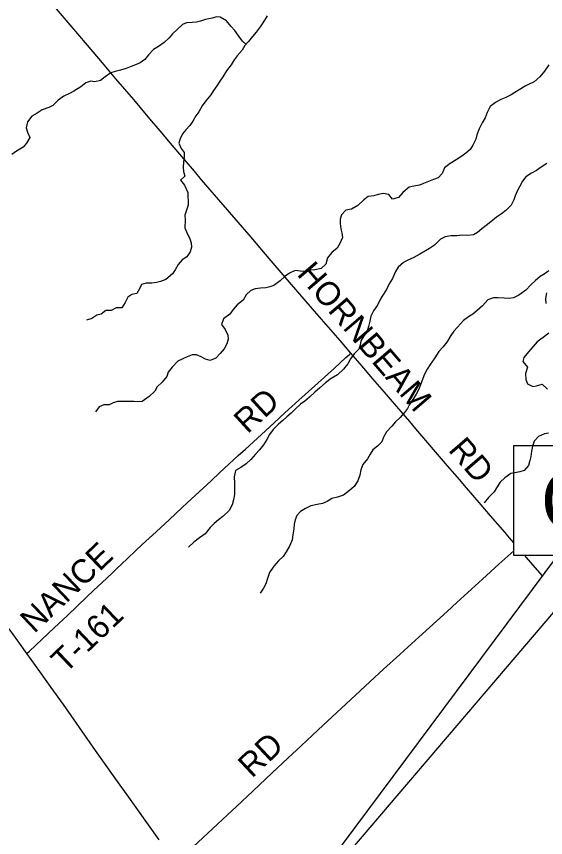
# Model space of a CAD drawing. Extents: x 0 to 34, y 0 to 22.
# Drawn here: x 5.101 to 6.367, y 18.098 to 20.064 of the extents above; entities that cross this region are included whole.
import ezdxf

# ---------------------------------------------------------------- set-up
doc = ezdxf.new("R2010")
doc.units = 0
for name, color, linetype in [('GM_X_Minor_River', 7, 'Continuous'), ('GM_X_State_Route', 7, 'Continuous'), ('GM_X_Township_Road', 7, 'Continuous'), ('GM_X_Township_Road_Text', 7, 'Continuous'), ('SH_Text', 7, 'Continuous')]:
    doc.layers.add(name, color=color, linetype=linetype)

msp = doc.modelspace()

# ---------------------------------------------------------------- linework, layer by layer
at = {"layer": 'GM_X_Minor_River'}
for points in [[(5.6499, 19.9972), (5.6422, 20.0042), (5.6332, 20.0168), (5.6234, 20.0298), (5.6148, 20.0397), (5.6035, 20.0535), (5.5887, 20.0616), (5.5793, 20.0628), (5.569, 20.0598), (5.553, 20.0561), (5.5412, 20.052), (5.5317, 20.0498), (5.521, 20.0488), (5.5081, 20.0485), (5.4982, 20.0444), (5.4852, 20.0327), (5.4741, 20.0222), (5.4665, 20.0124), (5.4542, 20.0011), (5.4405, 19.992), (5.4286, 19.9842), (5.4172, 19.9717), (5.4083, 19.9608), (5.3973, 19.9525), (5.3854, 19.948), (5.3755, 19.9439), (5.3634, 19.9391), (5.3496, 19.9354), (5.3375, 19.9317), (5.3268, 19.9283), (5.3134, 19.9189), (5.302, 19.9103), (5.2887, 19.9074), (5.2792, 19.9086), (5.2666, 19.9049), (5.2552, 19.8955), (5.238, 19.8849), (5.2277, 19.8793), (5.214, 19.873), (5.2006, 19.8636), (5.188, 19.8508), (5.1781, 19.8459), (5.1628, 19.8399), (5.1502, 19.8324), (5.1376, 19.8246), (5.1273, 19.8113), (5.1245, 19.7973), (5.1275, 19.7867), (5.1327, 19.7741), (5.125, 19.7605), (5.1166, 19.7507), (5.1009, 19.7409), (5.0902, 19.7334)], [(5.7012, 20.0649), (5.6919, 20.0509), (5.6843, 20.0392), (5.6743, 20.026), (5.6658, 20.0158), (5.6559, 20.0041), (5.6471, 19.9939), (5.6409, 19.983), (5.629, 19.9694), (5.6221, 19.9596), (5.6148, 19.9478), (5.6033, 19.9335), (5.5948, 19.9191), (5.5879, 19.9089), (5.5806, 19.8976), (5.5726, 19.8866), (5.566, 19.8764), (5.5538, 19.8617), (5.5453, 19.85), (5.5372, 19.8356), (5.5299, 19.8258), (5.523, 19.8126), (5.5161, 19.8024), (5.5061, 19.7926), (5.4981, 19.7824), (5.4923, 19.7703), (5.4895, 19.7601), (5.4951, 19.7475)], [(6.3747, 19.9479), (6.3647, 19.9324), (6.3532, 19.9188), (6.3398, 19.9075), (6.328, 19.9015), (6.3184, 19.8967), (6.3039, 19.8877), (6.294, 19.8817), (6.2845, 19.876), (6.2719, 19.8697), (6.2597, 19.8645), (6.2475, 19.8577), (6.2349, 19.8483), (6.2272, 19.8336), (6.2229, 19.8211), (6.2152, 19.8086), (6.2083, 19.7946), (6.2028, 19.7802), (6.2001, 19.77), (6.1932, 19.7556), (6.1866, 19.7454), (6.1767, 19.7367), (6.1668, 19.7292), (6.153, 19.7202), (6.1385, 19.7116), (6.1255, 19.701), (6.1193, 19.6874), (6.1101, 19.6772), (6.0987, 19.6735), (6.0873, 19.6683), (6.0747, 19.6638), (6.0652, 19.6601), (6.0515, 19.6575), (6.0409, 19.6553), (6.0259, 19.6425), (6.0148, 19.6301), (6.0011, 19.6264), (5.9917, 19.6371), (5.9781, 19.6399), (5.9667, 19.6377), (5.9564, 19.6343), (5.9423, 19.6325), (5.932, 19.6246), (5.9182, 19.6107), (5.9026, 19.6025), (5.8889, 19.5999), (5.8789, 19.589), (5.8754, 19.5784), (5.8757, 19.5681), (5.8772, 19.5548), (5.8794, 19.5453), (5.8815, 19.5343), (5.875, 19.5203), (5.8688, 19.5089), (5.8554, 19.4988), (5.8455, 19.4859), (5.8412, 19.4708), (5.8301, 19.4598), (5.8152, 19.4569), (5.8042, 19.4559), (5.7913, 19.4533), (5.7799, 19.4538), (5.7678, 19.455), (5.7544, 19.4494), (5.7437, 19.4415), (5.7319, 19.4306), (5.717, 19.4197), (5.7075, 19.4163), (5.6979, 19.4141), (5.6846, 19.4131), (5.6725, 19.4117), (5.6618, 19.4076), (5.6503, 19.3974), (5.6434, 19.3845), (5.6293, 19.3732), (5.6193, 19.3623), (5.6112, 19.3506), (5.596, 19.3397), (5.5917, 19.3264), (5.6003, 19.3139), (5.607, 19.3005), (5.6074, 19.2906), (5.6042, 19.2796), (5.5981, 19.2679), (5.5885, 19.2566), (5.5781, 19.2457), (5.5644, 19.2397), (5.5534, 19.2428), (5.5428, 19.2486)], [(5.4951, 19.7475), (5.5019, 19.7379), (5.5022, 19.7262), (5.5006, 19.7155), (5.4997, 19.7019), (5.5008, 19.6924), (5.5041, 19.681), (5.4938, 19.6716), (5.5032, 19.6597), (5.511, 19.6422), (5.5109, 19.6327), (5.5116, 19.6217), (5.5115, 19.6122), (5.5076, 19.5997), (5.5041, 19.5879), (5.5048, 19.5769), (5.5039, 19.5572), (5.5091, 19.5439), (5.5147, 19.5339), (5.5188, 19.5218), (5.5195, 19.5111), (5.5164, 19.5001), (5.5083, 19.4881), (5.4976, 19.4809), (5.488, 19.4696), (5.4811, 19.4571), (5.4745, 19.4473), (5.4585, 19.4337), (5.4459, 19.4293), (5.4364, 19.4263), (5.425, 19.4253), (5.4113, 19.4254), (5.3999, 19.4216), (5.3953, 19.4114), (5.3887, 19.4001), (5.3769, 19.3979), (5.3674, 19.3919), (5.3608, 19.3787), (5.3528, 19.3658), (5.3399, 19.3663), (5.3273, 19.3599), (5.3147, 19.3596), (5.304, 19.351), (5.2934, 19.3484), (5.2812, 19.3401), (5.2686, 19.3368)], [(6.3698, 19.7114), (6.3568, 19.7031), (6.3457, 19.6945), (6.3331, 19.6881), (6.3202, 19.6799), (6.3117, 19.6693), (6.3044, 19.6561), (6.2994, 19.6451), (6.2944, 19.6345), (6.2909, 19.6246), (6.2851, 19.6122), (6.2721, 19.5993), (6.2614, 19.5914), (6.2499, 19.5832), (6.2361, 19.5719), (6.2247, 19.5629), (6.2147, 19.5553), (6.2044, 19.5467), (6.1945, 19.5411), (6.1812, 19.5393), (6.1675, 19.5401), (6.1546, 19.5387), (6.1406, 19.5388), (6.1269, 19.5359), (6.1154, 19.5303), (6.1017, 19.5163), (6.0894, 19.508), (6.0795, 19.5028), (6.0662, 19.4945), (6.0501, 19.4859), (6.0372, 19.4803), (6.0273, 19.4747), (6.0143, 19.4634), (6.0077, 19.4528), (6.0008, 19.4366), (5.9931, 19.4233), (5.9865, 19.4097), (5.9761, 19.3942), (5.9707, 19.3844), (5.9646, 19.3727), (5.9554, 19.3591), (5.9492, 19.3458), (5.9464, 19.3341), (5.9437, 19.3212), (5.9402, 19.3098), (5.9317, 19.2973), (5.9252, 19.2871), (5.9232, 19.2769), (5.9201, 19.2671), (5.909, 19.2558), (5.9001, 19.244), (5.8943, 19.2316), (5.8832, 19.2195), (5.8691, 19.2055), (5.8542, 19.1969), (5.8404, 19.1864), (5.8267, 19.1744), (5.8152, 19.1642), (5.8022, 19.1521), (5.7911, 19.1423), (5.7808, 19.1352), (5.7678, 19.1232), (5.7582, 19.1141), (5.7479, 19.1047), (5.738, 19.0964), (5.728, 19.0874), (5.715, 19.0746), (5.7066, 19.0629), (5.7004, 19.0504), (5.6923, 19.0379), (5.6823, 19.0258), (5.6728, 19.0153), (5.662, 19.0032), (5.6506, 18.9927), (5.6376, 18.984), (5.625, 18.9765), (5.6218, 18.961), (5.6228, 18.9462), (5.6231, 18.9329), (5.623, 18.9192), (5.6206, 18.9063), (5.6175, 18.8946), (5.6098, 18.8806), (5.5949, 18.8666), (5.5846, 18.8584)], [(6.3746, 19.4543), (6.3639, 19.4468), (6.354, 19.4412), (6.3433, 19.4314), (6.3318, 19.4208), (6.3199, 19.408), (6.3035, 19.396), (6.2905, 19.39), (6.2803, 19.3882), (6.2677, 19.389), (6.2529, 19.3903), (6.2427, 19.3903), (6.2293, 19.3851), (6.2159, 19.3708), (6.2033, 19.3599), (6.1934, 19.3508), (6.1831, 19.3441), (6.1709, 19.3358), (6.1567, 19.3196), (6.1479, 19.3098), (6.1402, 19.2996), (6.131, 19.2837)], [(6.3692, 19.4016), (6.3668, 19.3887), (6.3675, 19.3761)], [(6.3753, 19.3051), (6.3615, 19.2949), (6.3467, 19.2848), (6.3378, 19.2731), (6.326, 19.2606), (6.3148, 19.2471), (6.3129, 19.2376), (6.3238, 19.2238), (6.3195, 19.2091), (6.3201, 19.1946), (6.3242, 19.1843), (6.3363, 19.1774), (6.3458, 19.1792), (6.3588, 19.1829), (6.3716, 19.1711)], [(6.131, 19.2837), (6.1214, 19.2716), (6.1118, 19.2611), (6.1022, 19.2463), (6.091, 19.2305), (6.0834, 19.2195), (6.0776, 19.207), (6.0737, 19.1968), (6.0679, 19.1813), (6.0632, 19.1696), (6.0578, 19.1594), (6.0509, 19.1488), (6.0413, 19.1348), (6.0367, 19.125), (6.0297, 19.1151), (6.019, 19.1034), (6.0079, 19.0929), (5.9991, 19.0827), (5.9861, 19.0695), (5.9795, 19.0563), (5.9756, 19.0453), (5.9653, 19.0347), (5.9538, 19.0257), (5.9473, 19.0155), (5.9408, 19.0042), (5.93, 18.991), (5.9254, 18.9781), (5.923, 18.9652), (5.9179, 18.952), (5.9087, 18.9384), (5.8976, 18.9289), (5.8835, 18.9177), (5.8694, 18.9128), (5.8553, 18.9091), (5.8446, 18.9024), (5.8336, 18.8979), (5.8207, 18.8953), (5.8054, 18.892), (5.7925, 18.8857), (5.7803, 18.8786), (5.7718, 18.8684), (5.7676, 18.8585), (5.7652, 18.8483), (5.7644, 18.8369), (5.7627, 18.8221), (5.7607, 18.8104), (5.7553, 18.7967), (5.7465, 18.782), (5.7392, 18.7703), (5.7284, 18.7601), (5.7166, 18.7473), (5.7066, 18.7326), (5.7015, 18.7178), (5.6976, 18.7053), (5.6922, 18.6947), (5.6838, 18.6826)], [(5.5428, 19.2486), (5.5319, 19.2532), (5.5216, 19.2533), (5.5098, 19.2485), (5.4988, 19.244), (5.4873, 19.238), (5.4739, 19.2237), (5.4639, 19.212), (5.4604, 19.2017), (5.4497, 19.1878), (5.4378, 19.1765), (5.4321, 19.1666), (5.4183, 19.1535), (5.4019, 19.1418), (5.3909, 19.1408), (5.3814, 19.1416), (5.3673, 19.1421), (5.3525, 19.1418), (5.343, 19.1415), (5.3327, 19.1385), (5.3228, 19.1337), (5.3103, 19.1334), (5.2985, 19.1289), (5.29, 19.1172)], [(6.3738, 19.0659), (6.3643, 19.0644), (6.3502, 19.0581), (6.3402, 19.0468), (6.3356, 19.035), (6.3336, 19.0229), (6.3316, 19.0104), (6.3296, 19.0002), (6.3261, 18.9884), (6.3161, 18.9767), (6.3058, 18.9734), (6.2937, 18.9708), (6.2842, 18.9694), (6.2693, 18.9588), (6.2589, 18.9487), (6.2501, 18.9351), (6.2439, 18.9252), (6.2309, 18.9117), (6.2202, 18.8988)], [(5.5846, 18.8584), (5.5742, 18.8497), (5.5647, 18.8399), (5.5528, 18.8252), (5.5386, 18.8154), (5.5256, 18.8053), (5.5126, 18.7932)]]:
    msp.add_lwpolyline(points, dxfattribs=at)
at = {"layer": 'GM_X_State_Route'}
msp.add_lwpolyline([(5.4426, 18.0921), (5.3875, 18.1696), (5.3657, 18.1999), (5.3425, 18.2321), (5.3197, 18.2647), (5.2903, 18.3063), (5.2648, 18.3431), (5.2322, 18.39), (5.2134, 18.4163), (5.184, 18.4571), (5.1567, 18.4949), (5.126, 18.5381), (5.1045, 18.5683), (5.0834, 18.5976)], dxfattribs=at)
at = {"layer": 'GM_X_Township_Road'}
for points in [[(5.9015, 19.2573), (5.8758, 19.2875), (5.831, 19.3391), (5.8094, 19.364), (5.739, 19.4452), (5.706, 19.484), (5.6575, 19.5406), (5.6311, 19.5712), (5.6209, 19.5829), (5.5953, 19.6126), (5.5751, 19.6362), (5.5441, 19.6726), (5.5268, 19.693), (5.492, 19.7343), (5.4698, 19.7603), (5.445, 19.7897), (5.4204, 19.8186), (5.3814, 19.8646), (5.3391, 19.9142), (5.3065, 19.9525), (5.2707, 19.9947), (5.2012, 20.0767), (5.1664, 20.1181)], [(5.126, 18.5381), (5.1321, 18.5438), (5.1912, 18.5997), (5.2227, 18.6297), (5.2682, 18.673), (5.2863, 18.69), (5.3058, 18.7083), (5.3289, 18.73), (5.341, 18.7415), (5.3523, 18.7522), (5.3676, 18.7668), (5.3856, 18.7839), (5.402, 18.7991), (5.4353, 18.83), (5.4671, 18.8596), (5.4818, 18.873), (5.4977, 18.8878), (5.5096, 18.8988), (5.5669, 18.9521), (5.5879, 18.9716), (5.6094, 18.9913), (5.6317, 19.0121), (5.6491, 19.028), (5.6871, 19.0629), (5.7179, 19.091), (5.7435, 19.1144), (5.777, 19.1451), (5.8609, 19.2209), (5.8895, 19.2467), (5.8979, 19.2541), (5.9015, 19.2573)], [(6.2913, 18.8031), (6.2807, 18.8154), (6.2766, 18.8201), (6.2701, 18.8277), (6.2352, 18.8681), (6.2127, 18.8947), (6.1731, 18.9409), (6.1617, 18.954), (6.1326, 18.988), (6.057, 19.0762), (6.0421, 19.0937), (6.0113, 19.1295), (5.9959, 19.1474), (5.9814, 19.1644), (5.9536, 19.1963), (5.9233, 19.2317), (5.9015, 19.2573)], [(5.4835, 18.0361), (5.4951, 18.0472), (5.5055, 18.0579), (5.5234, 18.0751), (5.582, 18.1299), (5.6057, 18.1518), (5.6276, 18.172), (5.6664, 18.2087), (5.7125, 18.2523), (5.7503, 18.2874), (5.7819, 18.3173), (5.8228, 18.3554), (5.8901, 18.4181), (5.9581, 18.4809), (5.9796, 18.5007), (6.0181, 18.5359), (6.0287, 18.5455), (6.0638, 18.5772), (6.1316, 18.6392), (6.1545, 18.6602), (6.2166, 18.7166), (6.2556, 18.7523), (6.2913, 18.7845)], [(6.3598, 18.724), (6.3425, 18.7441), (6.3218, 18.768), (6.3172, 18.7733)]]:
    msp.add_lwpolyline(points, dxfattribs=at)
at = {"layer": 'SH_Text'}
msp.add_lwpolyline([(6.2913, 19.0362), (7.4233, 19.0362), (7.4233, 18.7733), (6.5017, 18.7733), (5.6692, 17.796), (6.3965, 18.7733), (6.2913, 18.7733)], close=True, dxfattribs=at)

# ---------------------------------------------------------------- texts
at = {"layer": 'GM_X_Township_Road_Text'}
for s, rotation, p in [('HORNBEAM', 310.6273, (5.7701, 19.4456)), ('RD', 42.5707, (5.6538, 19.0626)), ('RD', 310.8176, (6.1324, 19.0249)), ('NANCE', 43.5958, (5.1435, 18.5847)), ('T-161', 43.6196, (5.2177, 18.4888)), ('RD', 43.2429, (5.6643, 18.2381))]:
    msp.add_text(s, height=0.05682, rotation=rotation, dxfattribs=at).set_placement(p)
at = {"layer": 'SH_Text'}
msp.add_text('CLI-72-2.18', height=0.14, dxfattribs=at).set_placement((6.356, 18.8347))

doc.saveas('drawing.dxf')
